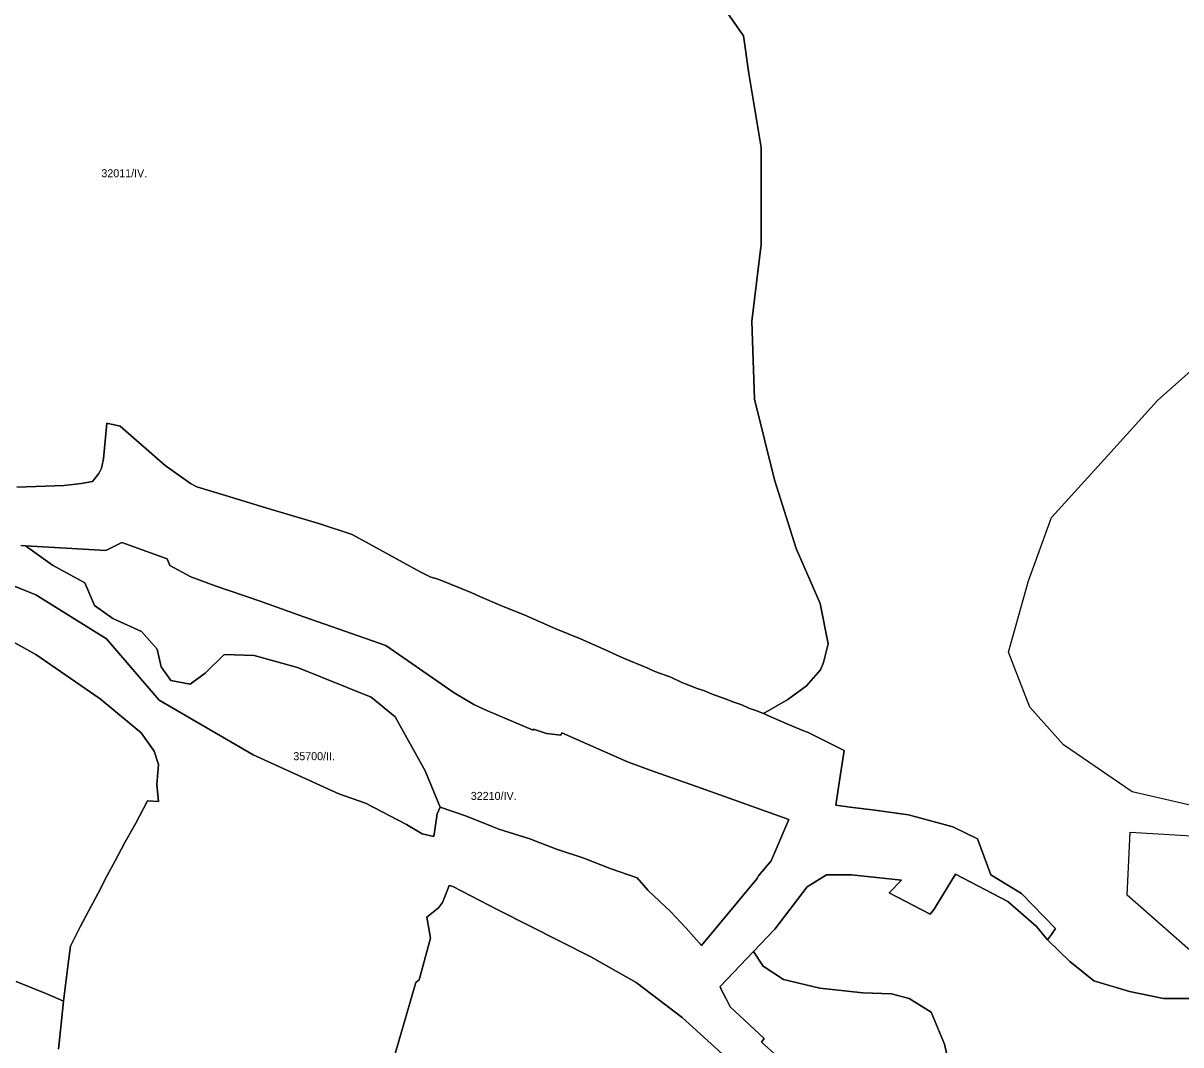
# Model space of a CAD drawing. Extents: x -521621 to -516761, y -1190184 to -1184927.
# Drawn here: x -518790 to -518211, y -1187445 to -1186934 of the extents above; entities that cross this region are included whole.
import ezdxf

# ---------------------------------------------------------------- set-up
doc = ezdxf.new("R2010")
doc.units = 0
doc.layers.add('BPEJ_s', color=7, linetype='Continuous')
doc.layers.add('odvodneni_s', color=7, linetype='Continuous')

msp = doc.modelspace()

# ---------------------------------------------------------------- linework, layer by layer
at = {"layer": 'BPEJ_s'}
for p, q in [((-518749.45, -1187151.67), (-518747.8, -1187133.89)), ((-518747.8, -1187133.89), (-518741.03, -1187135.41)), ((-518741.03, -1187135.41), (-518718.63, -1187154.97)), ((-518750.33, -1187156.28), (-518749.45, -1187151.67)), ((-518751.77, -1187159.04), (-518750.33, -1187156.28)), ((-518718.63, -1187154.97), (-518705.85, -1187164.02)), ((-518760.63, -1187163.99), (-518754.88, -1187162.95)), ((-518754.88, -1187162.95), (-518751.77, -1187159.04)), ((-518792.7, -1187165.88), (-518769.12, -1187164.94)), ((-518769.12, -1187164.94), (-518760.63, -1187163.99)), ((-518705.85, -1187164.02), (-518702.78, -1187165.74)), ((-518702.78, -1187165.74), (-518688.38, -1187169.96)), ((-518688.38, -1187169.96), (-518668.2, -1187176.14)), ((-518668.2, -1187176.14), (-518641.27, -1187184.22)), ((-518641.27, -1187184.22), (-518625.13, -1187189.42)), ((-518625.13, -1187189.42), (-518591.15, -1187208.13)), ((-518788.41, -1187195.16), (-518790.68, -1187195.03)), ((-518765.2, -1187196.45), (-518788.41, -1187195.16)), ((-518748.24, -1187197.55), (-518765.2, -1187196.45)), ((-518740.14, -1187193.42), (-518748.24, -1187197.55)), ((-518717.55, -1187201.72), (-518740.14, -1187193.42)), ((-518716.17, -1187205.03), (-518717.55, -1187201.72)), ((-518705.68, -1187210.59), (-518716.17, -1187205.03)), ((-518591.15, -1187208.13), (-518585.8, -1187210.8)), ((-518806.02, -1187210.57), (-518783.14, -1187219.65)), ((-518693.5, -1187215.16), (-518705.68, -1187210.59)), ((-518671.13, -1187222.76), (-518693.5, -1187215.16)), ((-518585.8, -1187210.8), (-518582.06, -1187211.88)), ((-518582.06, -1187211.88), (-518565.21, -1187218.57)), ((-518783.14, -1187219.65), (-518747.81, -1187241.68)), ((-518565.21, -1187218.57), (-518561.19, -1187220.44)), ((-518561.19, -1187220.44), (-518550.46, -1187225.18)), ((-518652.08, -1187229.66), (-518671.13, -1187222.76)), ((-518550.46, -1187225.18), (-518539.09, -1187229.68)), ((-518649.26, -1187230.68), (-518652.08, -1187229.66)), ((-518608.3, -1187244.95), (-518649.26, -1187230.68)), ((-518539.09, -1187229.68), (-518523.23, -1187236.56)), ((-518783.14, -1187249.42), (-518811.5, -1187233.85)), ((-518523.23, -1187236.56), (-518510.96, -1187241.66)), ((-518747.81, -1187241.68), (-518721.57, -1187272.27)), ((-518510.96, -1187241.66), (-518500.78, -1187246.15)), ((-518750.97, -1187271.58), (-518783.14, -1187249.42)), ((-518574.05, -1187268.63), (-518608.3, -1187244.95)), ((-518500.78, -1187246.15), (-518489.41, -1187251.24)), ((-518489.41, -1187251.24), (-518477.23, -1187256.32)), ((-518477.23, -1187256.32), (-518475.34, -1187257.27)), ((-518475.34, -1187257.27), (-518473.29, -1187258.06)), ((-518473.29, -1187258.06), (-518465.87, -1187260.74)), ((-518465.87, -1187260.74), (-518460.35, -1187263.43)), ((-518460.35, -1187263.43), (-518456.88, -1187264.85)), ((-518456.88, -1187264.85), (-518453.09, -1187266.27)), ((-518453.09, -1187266.27), (-518448.99, -1187267.69)), ((-518730.57, -1187288.54), (-518750.97, -1187271.58)), ((-518721.57, -1187272.27), (-518674.53, -1187299.62)), ((-518564.27, -1187274.45), (-518574.05, -1187268.63)), ((-518448.99, -1187267.69), (-518445.2, -1187269.27)), ((-518445.2, -1187269.27), (-518438.1, -1187271.8)), ((-518438.1, -1187271.8), (-518434.31, -1187273.22)), ((-518557.45, -1187277.54), (-518564.27, -1187274.45)), ((-518534.6, -1187287.31), (-518557.45, -1187277.54)), ((-518434.31, -1187273.22), (-518430.37, -1187274.64)), ((-518430.37, -1187274.64), (-518426.74, -1187276.22)), ((-518426.74, -1187276.22), (-518423.27, -1187277.48)), ((-518423.27, -1187277.48), (-518419.48, -1187278.9)), ((-518419.48, -1187278.9), (-518415.85, -1187280.64)), ((-518415.85, -1187280.64), (-518408.12, -1187283.95)), ((-518408.12, -1187283.95), (-518400.71, -1187287.11)), ((-518724.01, -1187297.86), (-518730.57, -1187288.54)), ((-518534.37, -1187286.74), (-518534.6, -1187287.31)), ((-518527.99, -1187288.9), (-518534.37, -1187286.74)), ((-518520.79, -1187289.73), (-518527.99, -1187288.9)), ((-518520.23, -1187288.6), (-518520.79, -1187289.73)), ((-518487.5, -1187303.07), (-518520.23, -1187288.6)), ((-518400.71, -1187287.11), (-518397.08, -1187288.53)), ((-518397.08, -1187288.53), (-518392.82, -1187290.59)), ((-518392.82, -1187290.59), (-518379.21, -1187297.43)), ((-518721.97, -1187304.42), (-518724.01, -1187297.86)), ((-518674.53, -1187299.62), (-518631.7, -1187319.15)), ((-518379.21, -1187297.43), (-518381.66, -1187313.52)), ((-518722.65, -1187314.38), (-518721.97, -1187304.42)), ((-518474.37, -1187307.86), (-518487.5, -1187303.07)), ((-518452.92, -1187315.38), (-518474.37, -1187307.86)), ((-518381.66, -1187313.52), (-518383.28, -1187324.68)), ((-518721.97, -1187322.97), (-518722.65, -1187314.38)), ((-518631.7, -1187319.15), (-518618.41, -1187323.77)), ((-518406.88, -1187331.85), (-518452.92, -1187315.38)), ((-518733.28, -1187333.83), (-518727.4, -1187322.52)), ((-518727.4, -1187322.52), (-518721.97, -1187322.97)), ((-518618.41, -1187323.77), (-518597.96, -1187334.49)), ((-518383.28, -1187324.68), (-518376.08, -1187325.84)), ((-518584.29, -1187340.34), (-518582.52, -1187329.15)), ((-518582.52, -1187329.15), (-518581.08, -1187325.73)), ((-518581.08, -1187325.73), (-518568.02, -1187330.31)), ((-518568.02, -1187330.31), (-518555.15, -1187335.4)), ((-518376.08, -1187325.84), (-518363.77, -1187327.24)), ((-518363.77, -1187327.24), (-518347.05, -1187329.56)), ((-518347.05, -1187329.56), (-518326.61, -1187335.14)), ((-518738.7, -1187343.45), (-518733.28, -1187333.83)), ((-518597.96, -1187334.49), (-518590.11, -1187339.13)), ((-518555.15, -1187335.4), (-518551.81, -1187336.78)), ((-518551.81, -1187336.78), (-518536.31, -1187341.51)), ((-518415.68, -1187352.64), (-518406.88, -1187331.85)), ((-518326.61, -1187335.14), (-518324.85, -1187335.62)), ((-518324.85, -1187335.62), (-518312.54, -1187341.67)), ((-518590.11, -1187339.13), (-518584.29, -1187340.34)), ((-518536.31, -1187341.51), (-518522.98, -1187346.72)), ((-518312.54, -1187341.67), (-518305.87, -1187359.59)), ((-518743.56, -1187352.5), (-518738.7, -1187343.45)), ((-518522.98, -1187346.72), (-518509.26, -1187351.3)), ((-518747.52, -1187359.86), (-518743.56, -1187352.5)), ((-518509.26, -1187351.3), (-518496.17, -1187356.39)), ((-518421.94, -1187360.16), (-518415.68, -1187352.64)), ((-518752.27, -1187369.02), (-518747.52, -1187359.86)), ((-518496.17, -1187356.39), (-518482.71, -1187361.04)), ((-518388.07, -1187359.56), (-518397.65, -1187365.6)), ((-518375.56, -1187359.56), (-518388.07, -1187359.56)), ((-518350.53, -1187362.26), (-518375.56, -1187359.56)), ((-518323.54, -1187359.27), (-518334.16, -1187376.8)), ((-518297.29, -1187372.85), (-518323.54, -1187359.27)), ((-518305.87, -1187359.59), (-518290.5, -1187368.95)), ((-518576.6, -1187364.85), (-518577.92, -1187368.37)), ((-518574.79, -1187365.41), (-518576.6, -1187364.85)), ((-518552.25, -1187377.02), (-518574.79, -1187365.41)), ((-518482.71, -1187361.04), (-518477.11, -1187367.35)), ((-518450.45, -1187394.81), (-518422.64, -1187361.41)), ((-518422.64, -1187361.41), (-518421.94, -1187360.16)), ((-518397.65, -1187365.6), (-518413.74, -1187386.66)), ((-518356.7, -1187368.61), (-518350.53, -1187362.26)), ((-518756.96, -1187377.73), (-518752.27, -1187369.02)), ((-518577.92, -1187368.37), (-518579.86, -1187373.34)), ((-518477.11, -1187367.35), (-518471.23, -1187372.96)), ((-518336.09, -1187379.3), (-518356.7, -1187368.61)), ((-518290.5, -1187368.95), (-518273.44, -1187386.43)), ((-518581.86, -1187376.01), (-518587.71, -1187380.66)), ((-518579.86, -1187373.34), (-518581.86, -1187376.01)), ((-518505.78, -1187400.57), (-518552.25, -1187377.02)), ((-518471.23, -1187372.96), (-518466.02, -1187377.83)), ((-518334.16, -1187376.8), (-518336.09, -1187379.3)), ((-518283.06, -1187385.33), (-518297.29, -1187372.85)), ((-518761.11, -1187385.61), (-518756.96, -1187377.73)), ((-518587.71, -1187380.66), (-518586, -1187391.15)), ((-518466.02, -1187377.83), (-518458.09, -1187386.18)), ((-518765.94, -1187395.16), (-518761.11, -1187385.61)), ((-518458.09, -1187386.18), (-518450.45, -1187394.81)), ((-518413.74, -1187386.66), (-518424.47, -1187397.86)), ((-518277.49, -1187392.12), (-518283.06, -1187385.33)), ((-518273.44, -1187386.43), (-518275.52, -1187389.38)), ((-518586, -1187391.15), (-518591.57, -1187412.05)), ((-518275.52, -1187389.38), (-518277.49, -1187392.12)), ((-518767.05, -1187404.01), (-518765.94, -1187395.16)), ((-518424.47, -1187397.86), (-518441.19, -1187415.31)), ((-518768.43, -1187414.67), (-518767.05, -1187404.01)), ((-518483.12, -1187413.42), (-518505.78, -1187400.57)), ((-518591.57, -1187412.05), (-518593.3, -1187413.32)), ((-518792.98, -1187412.81), (-518777.4, -1187419.2)), ((-518769.31, -1187422.77), (-518768.43, -1187414.67)), ((-518593.3, -1187413.32), (-518606.43, -1187458.65)), ((-518460.08, -1187430.81), (-518483.12, -1187413.42)), ((-518441.19, -1187415.31), (-518440.44, -1187417.2)), ((-518440.44, -1187417.2), (-518438.4, -1187420.8)), ((-518777.4, -1187419.2), (-518769.31, -1187422.77)), ((-518769.31, -1187422.77), (-518770.52, -1187434)), ((-518770.52, -1187434), (-518769.31, -1187422.77)), ((-518438.4, -1187420.8), (-518436.21, -1187425.62)), ((-518436.21, -1187425.62), (-518419.15, -1187441.39)), ((-518770.52, -1187434), (-518771.89, -1187446.71)), ((-518771.89, -1187446.71), (-518770.52, -1187434)), ((-518440.06, -1187448.96), (-518460.08, -1187430.81)), ((-518419.15, -1187441.39), (-518420.46, -1187443.14)), ((-518420.46, -1187443.14), (-518412.59, -1187450.15))]:
    msp.add_line(p, q, dxfattribs=at)
for points in [[(-518450.92, -1186909.41), (-518429.42, -1186940.33), (-518426.74, -1186959.16), (-518420.69, -1186996.13), (-518420.69, -1187044.54), (-518425.39, -1187082.86), (-518424.05, -1187121.85), (-518413.97, -1187162.19), (-518403.22, -1187196.47), (-518391.13, -1187224.04), (-518387.1, -1187244.2), (-518389.55, -1187253.44), (-518391.06, -1187257.16), (-518397.92, -1187265.06), (-518407.32, -1187271.92), (-518419.48, -1187278.9), (-518423.27, -1187277.48), (-518426.74, -1187276.22), (-518430.37, -1187274.64), (-518434.31, -1187273.22), (-518438.1, -1187271.8), (-518445.2, -1187269.27), (-518448.99, -1187267.69), (-518453.09, -1187266.27), (-518456.88, -1187264.85), (-518460.35, -1187263.43), (-518465.87, -1187260.74), (-518473.29, -1187258.06), (-518475.34, -1187257.27), (-518477.23, -1187256.32), (-518489.41, -1187251.24), (-518500.78, -1187246.15), (-518510.96, -1187241.66), (-518523.23, -1187236.56), (-518539.09, -1187229.68), (-518550.46, -1187225.18), (-518561.19, -1187220.44), (-518565.21, -1187218.57), (-518582.06, -1187211.88), (-518585.8, -1187210.8), (-518591.15, -1187208.13), (-518625.13, -1187189.42), (-518641.27, -1187184.22), (-518668.2, -1187176.14), (-518688.38, -1187169.96), (-518702.78, -1187165.74), (-518705.85, -1187164.02), (-518718.63, -1187154.97), (-518741.03, -1187135.41), (-518747.8, -1187133.89), (-518749.45, -1187151.67), (-518750.33, -1187156.28), (-518751.77, -1187159.04), (-518754.88, -1187162.95), (-518760.63, -1187163.99), (-518769.12, -1187164.94), (-518792.7, -1187165.88)], [(-518195.69, -1187421.38), (-518219.49, -1187421.38), (-518236.54, -1187417.83), (-518254.3, -1187412.5), (-518266.38, -1187402.9), (-518277.49, -1187392.12), (-518275.52, -1187389.38), (-518273.44, -1187386.43), (-518290.5, -1187368.95), (-518305.87, -1187359.59), (-518312.54, -1187341.67), (-518324.85, -1187335.62), (-518326.61, -1187335.14), (-518347.05, -1187329.56), (-518363.77, -1187327.24), (-518376.08, -1187325.84), (-518383.28, -1187324.68), (-518381.66, -1187313.52), (-518379.21, -1187297.43), (-518392.82, -1187290.59), (-518397.08, -1187288.53), (-518400.71, -1187287.11), (-518408.12, -1187283.95), (-518415.85, -1187280.64), (-518419.48, -1187278.9), (-518407.32, -1187271.92), (-518397.92, -1187265.06), (-518391.06, -1187257.16), (-518389.55, -1187253.44), (-518387.1, -1187244.2), (-518391.13, -1187224.04), (-518403.22, -1187196.47), (-518413.97, -1187162.19), (-518424.05, -1187121.85), (-518425.39, -1187082.86), (-518420.69, -1187044.54), (-518420.69, -1186996.13), (-518426.74, -1186959.16), (-518429.42, -1186940.33), (-518450.92, -1186909.41)], [(-518199.64, -1187326.22), (-518235.25, -1187318.15), (-518269.52, -1187294.62), (-518286.31, -1187275.8), (-518297.06, -1187248.24), (-518286.99, -1187212.61), (-518275.56, -1187181.01), (-518247.35, -1187150.08), (-518222.49, -1187122.52), (-518196.96, -1187099.66)], [(-518199.64, -1187326.22), (-518235.25, -1187318.15), (-518269.52, -1187294.62), (-518286.31, -1187275.8), (-518297.06, -1187248.24), (-518286.99, -1187212.61), (-518275.56, -1187181.01), (-518247.35, -1187150.08), (-518222.49, -1187122.52), (-518196.96, -1187099.66)], [(-518790.68, -1187195.03), (-518788.41, -1187195.16), (-518774.8, -1187204.76), (-518758.75, -1187213.65), (-518753.96, -1187224.93), (-518744.74, -1187231.43), (-518730.39, -1187237.92), (-518722.53, -1187246.81), (-518720.48, -1187255.7), (-518715.69, -1187262.54), (-518706.13, -1187264.25), (-518698.61, -1187258.78), (-518689.04, -1187249.55), (-518674.01, -1187249.89), (-518652.48, -1187256.04), (-518615.58, -1187270.75), (-518603.62, -1187280.66), (-518588.59, -1187307.67), (-518581.08, -1187325.73), (-518582.52, -1187329.15), (-518584.29, -1187340.34), (-518590.11, -1187339.13), (-518597.96, -1187334.49), (-518618.41, -1187323.77), (-518631.7, -1187319.15), (-518674.53, -1187299.62), (-518721.57, -1187272.27), (-518747.81, -1187241.68), (-518783.14, -1187219.65), (-518806.02, -1187210.57)], [(-518811.5, -1187233.85), (-518783.14, -1187249.42), (-518750.97, -1187271.58), (-518730.57, -1187288.54), (-518724.01, -1187297.86), (-518721.97, -1187304.42), (-518722.65, -1187314.38), (-518721.97, -1187322.97), (-518727.4, -1187322.52), (-518733.28, -1187333.83), (-518738.7, -1187343.45), (-518743.56, -1187352.5), (-518747.52, -1187359.86), (-518752.27, -1187369.02), (-518756.96, -1187377.73), (-518761.11, -1187385.61), (-518765.94, -1187395.16), (-518767.05, -1187404.01), (-518768.43, -1187414.67), (-518769.31, -1187422.77), (-518777.4, -1187419.2), (-518792.98, -1187412.81)], [(-518319.17, -1187487.68), (-518329.08, -1187444.28), (-518335.59, -1187428.16), (-518346.74, -1187421.33), (-518355.58, -1187419.01), (-518369.83, -1187418.55), (-518391.36, -1187416.22), (-518409.49, -1187411.88), (-518419.71, -1187405.22), (-518424.47, -1187397.86), (-518413.74, -1187386.66), (-518397.65, -1187365.6), (-518388.07, -1187359.56), (-518375.56, -1187359.56), (-518350.53, -1187362.26), (-518356.7, -1187368.61), (-518336.09, -1187379.3), (-518334.16, -1187376.8), (-518323.54, -1187359.27), (-518297.29, -1187372.85), (-518283.06, -1187385.33), (-518277.49, -1187392.12), (-518266.38, -1187402.9), (-518254.3, -1187412.5), (-518236.54, -1187417.83), (-518219.49, -1187421.38), (-518195.69, -1187421.38)], [(-518606.43, -1187458.65), (-518593.3, -1187413.32), (-518591.57, -1187412.05), (-518586, -1187391.15), (-518587.71, -1187380.66), (-518581.86, -1187376.01), (-518579.86, -1187373.34), (-518577.92, -1187368.37), (-518576.6, -1187364.85), (-518574.79, -1187365.41), (-518552.25, -1187377.02), (-518505.78, -1187400.57), (-518483.12, -1187413.42), (-518460.08, -1187430.81), (-518440.06, -1187448.96)], [(-518412.59, -1187450.15), (-518420.46, -1187443.14), (-518419.15, -1187441.39), (-518436.21, -1187425.62), (-518438.4, -1187420.8), (-518440.44, -1187417.2), (-518441.19, -1187415.31), (-518424.47, -1187397.86), (-518419.71, -1187405.22), (-518409.49, -1187411.88), (-518391.36, -1187416.22), (-518369.83, -1187418.55), (-518355.58, -1187419.01), (-518346.74, -1187421.33), (-518335.59, -1187428.16), (-518329.08, -1187444.28), (-518319.17, -1187487.68)]]:
    msp.add_lwpolyline(points, dxfattribs=at)
msp.add_lwpolyline([(-518788.41, -1187195.16), (-518765.2, -1187196.45), (-518748.24, -1187197.55), (-518740.14, -1187193.42), (-518717.55, -1187201.72), (-518716.17, -1187205.03), (-518705.68, -1187210.59), (-518693.5, -1187215.16), (-518671.13, -1187222.76), (-518652.08, -1187229.66), (-518649.26, -1187230.68), (-518608.3, -1187244.95), (-518574.05, -1187268.63), (-518564.27, -1187274.45), (-518557.45, -1187277.54), (-518534.6, -1187287.31), (-518534.37, -1187286.74), (-518527.99, -1187288.9), (-518520.79, -1187289.73), (-518520.23, -1187288.6), (-518487.5, -1187303.07), (-518474.37, -1187307.86), (-518452.92, -1187315.38), (-518406.88, -1187331.85), (-518415.68, -1187352.64), (-518421.94, -1187360.16), (-518422.64, -1187361.41), (-518450.45, -1187394.81), (-518458.09, -1187386.18), (-518466.02, -1187377.83), (-518471.23, -1187372.96), (-518477.11, -1187367.35), (-518482.71, -1187361.04), (-518496.17, -1187356.39), (-518509.26, -1187351.3), (-518522.98, -1187346.72), (-518536.31, -1187341.51), (-518551.81, -1187336.78), (-518555.15, -1187335.4), (-518568.02, -1187330.31), (-518581.08, -1187325.73), (-518588.59, -1187307.67), (-518603.62, -1187280.66), (-518615.58, -1187270.75), (-518652.48, -1187256.04), (-518674.01, -1187249.89), (-518689.04, -1187249.55), (-518698.61, -1187258.78), (-518706.13, -1187264.25), (-518715.69, -1187262.54), (-518720.48, -1187255.7), (-518722.53, -1187246.81), (-518730.39, -1187237.92), (-518744.74, -1187231.43), (-518753.96, -1187224.93), (-518758.75, -1187213.65), (-518774.8, -1187204.76)], close=True, dxfattribs=at)
at = {"layer": 'odvodneni_s'}
msp.add_lwpolyline([(-518195.14, -1187407), (-518237.7, -1187369.82), (-518236.16, -1187338.27), (-518199.87, -1187340.38), (-518173.8, -1187344.62), (-518113.74, -1187347.57), (-518081.32, -1187351.71), (-518067.11, -1187359.78)], dxfattribs=at)

# ---------------------------------------------------------------- texts
at = {"layer": 'BPEJ_s'}
for s, p in [('32011/IV.', (-518750.45, -1187010.97)), ('35700/II.', (-518654.5, -1187302.28)), ('32210/IV.', (-518565.79, -1187322.13))]:
    msp.add_text(s, height=4, dxfattribs=at).set_placement(p)

doc.saveas('drawing.dxf')
